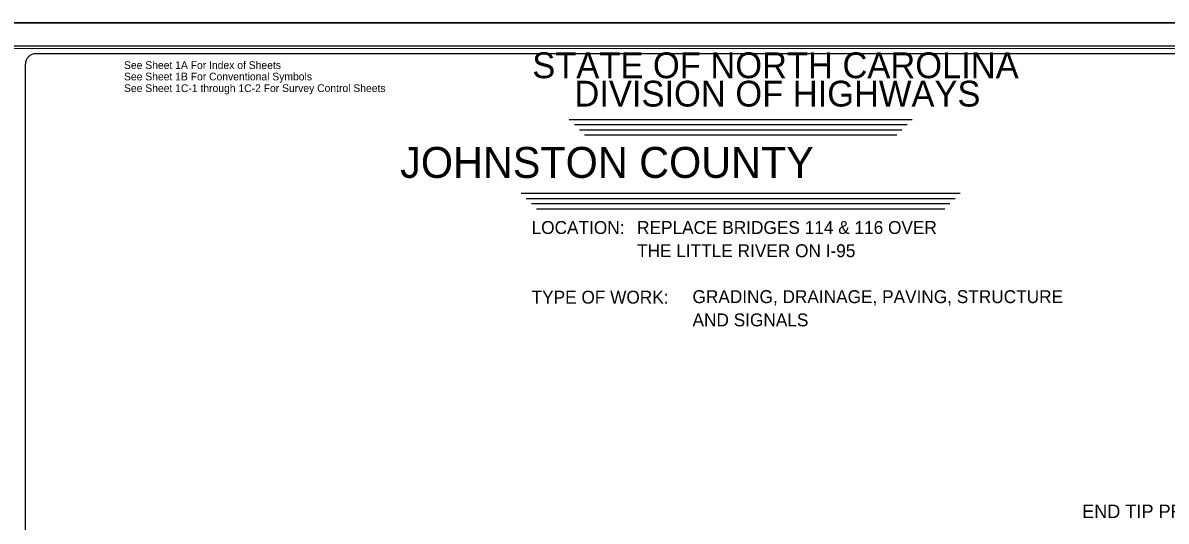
# Model space of a CAD drawing. Extents: x 2241278 to 2254132, y 649924 to 670434.
# Drawn here: x 2245656 to 2251201, y 663984 to 666399 of the extents above; entities that cross this region are included whole.
import ezdxf

# ---------------------------------------------------------------- set-up
doc = ezdxf.new("R2010")
doc.units = 0
for name, color, linetype in [('Prop RDY Alternate Text Yellow', 7, 'Continuous'), ('Sheet Cutting Line CELL', 7, 'Continuous'), ('Sheet Data Field CELL', 7, 'Continuous'), ('Sheet Plot Border Inside CELL', 7, 'Continuous'), ('Sheet Plot Border Outside CELL', 7, 'Continuous'), ('Sheet Title CELL', 7, 'Continuous'), ('Sheet Title Data Points CELL', 7, 'Continuous')]:
    doc.layers.add(name, color=color, linetype=linetype)

msp = doc.modelspace()

# ---------------------------------------------------------------- linework, layer by layer
at = {"layer": 'Sheet Cutting Line CELL'}
msp.add_line((2244558.8, 666399.1), (2252978.8, 666399.1), dxfattribs=at)
at = {"layer": 'Sheet Plot Border Inside CELL'}
msp.add_lwpolyline([(2244623.8, 661011.4), (2252956.3, 661011.4), (2252956.3, 666286.9), (2244623.8, 666286.9)], close=True, dxfattribs=at)
at = {"layer": 'Sheet Plot Border Outside CELL'}
msp.add_lwpolyline([(2252978.8, 666399.1), (2244558.8, 666399.1), (2244558.8, 660899.2), (2252978.8, 660899.2)], close=True, dxfattribs=at)
at = {"layer": 'Sheet Title CELL'}
for p, q in [((2245668.8, 662024.2), (2245668.8, 666199.2)), ((2248305.8, 665931.4), (2249969.5, 665931.4)), ((2248330.8, 665906.4), (2249944.5, 665906.4)), ((2248355.8, 665881.4), (2249919.5, 665881.4)), ((2248380.8, 665856.4), (2249894.5, 665856.4)), ((2248072.5, 665573.4), (2250202.5, 665573.4)), ((2248097.5, 665548.4), (2250177.5, 665548.4)), ((2248122.5, 665523.4), (2250152.5, 665523.4)), ((2248147.5, 665498.4), (2250127.5, 665498.4))]:
    msp.add_line(p, q, dxfattribs=at)
for points in [[(2252843.8, 666274.1), (2245443.7, 666274.2)], [(2252818.8, 666249.1), (2245718.8, 666249.1)]]:
    msp.add_lwpolyline(points, dxfattribs=at)
msp.add_arc((2245718.8, 666199.4), 50, 90, 180, dxfattribs=at)
at = {"layer": 'Sheet Title Data Points CELL'}
for p, q in [((2249145.3, 665647.9), (2249145.3, 665647.9)), ((2249745.5, 665376.1), (2249745.5, 665376.1))]:
    msp.add_line(p, q, dxfattribs=at)

# ---------------------------------------------------------------- texts
at = {"layer": 'Prop RDY Alternate Text Yellow'}
msp.add_text('END TIP PROJECT I-3318BB -L- 38+00.00', height=65.626, dxfattribs=at).set_placement((2250793.4, 663999.1))
at = {"layer": 'Sheet Data Field CELL'}
for s, height, p in [('       JOHNSTON COUNTY       ', 150, (2247096.2, 665647.9)), ('REPLACE BRIDGES 114 & 116 OVER', 62.501, (2248634.9, 665376.2)), ('THE LITTLE RIVER ON I-95', 62.501, (2248634.9, 665263.7)), ('GRADING, DRAINAGE, PAVING, STRUCTURE', 62.501, (2248903.8, 665041)), ('AND SIGNALS', 62.501, (2248903.9, 664928.4))]:
    msp.add_text(s, height=height, dxfattribs=at).set_placement(p)
at = {"layer": 'Sheet Title CELL'}
for s, height, p in [('STATE OF NORTH CAROLINA', 124.999, (2248126.8, 666131.1)), ('See Sheet 1A For Index of Sheets', 37.5, (2246146.9, 666175.6)), ('See Sheet 1B For Conventional Symbols', 37.5, (2246146.9, 666120.4)), ('DIVISION OF HIGHWAYS', 124.999, (2248331.3, 665993.7)), ('LOCATION: ', 62.5, (2248123.5, 665376.2)), ('TYPE OF WORK:', 62.501, (2248123.5, 665038.6))]:
    msp.add_text(s, height=height, rotation=360, dxfattribs=at).set_placement(p)
msp.add_text('See Sheet 1C-1 through 1C-2 For Survey Control Sheets', height=37.5, dxfattribs=at).set_placement((2246146.9, 666063.9))

doc.saveas('drawing.dxf')
